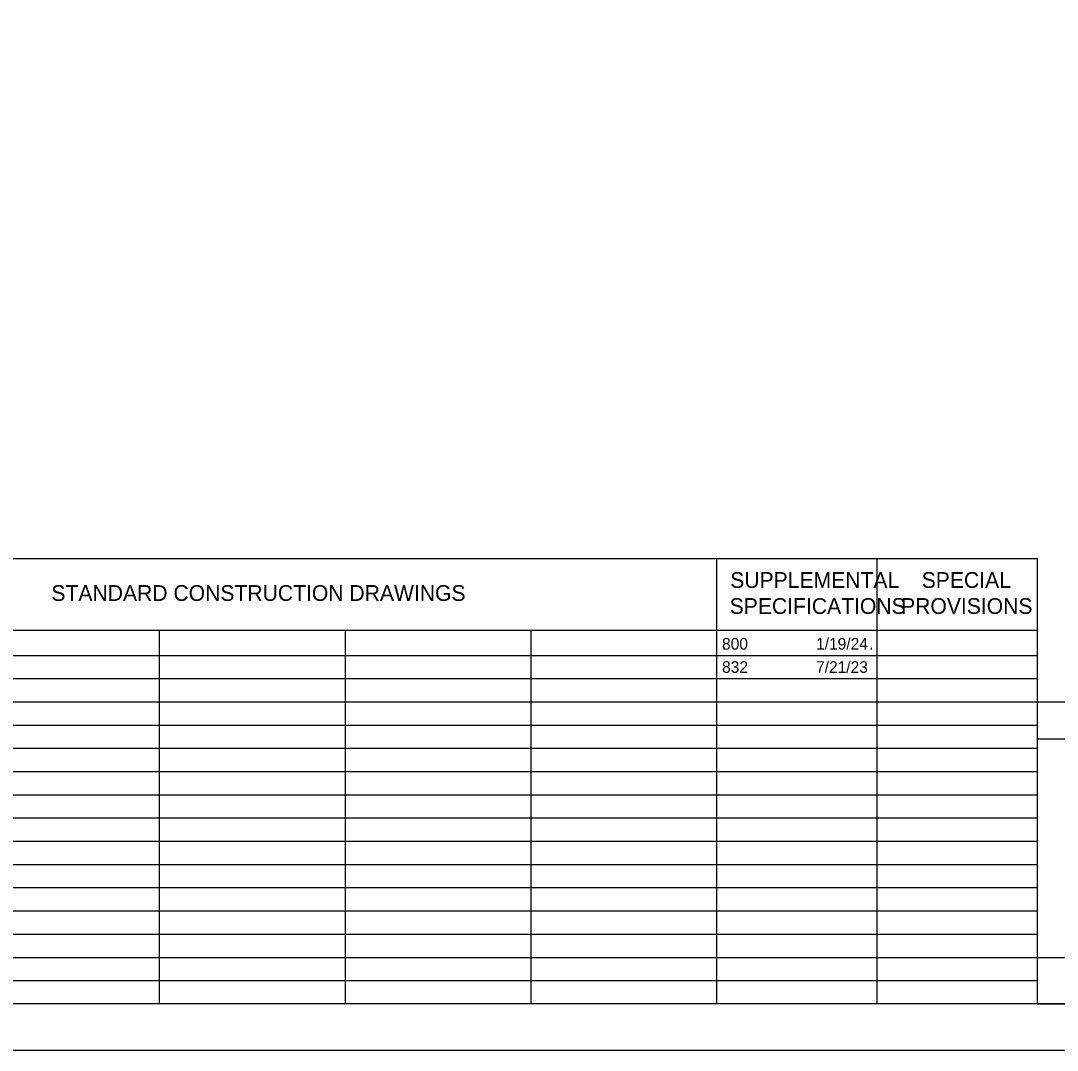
# Model space of a CAD drawing. Extents: x 0 to 34, y 0 to 22.
# Drawn here: x 12.66 to 23.81, y 0 to 11.08 of the extents above; entities that cross this region are included whole.
import ezdxf

# ---------------------------------------------------------------- set-up
doc = ezdxf.new("R2010")
doc.units = 0
for name, color, linetype in [('SH_Border', 7, 'Continuous'), ('SH_Cut_Line', 7, 'Continuous'), ('SH_Data', 7, 'Continuous'), ('SH_Text', 7, 'Continuous')]:
    doc.layers.add(name, color=color, linetype=linetype)

msp = doc.modelspace()

# ---------------------------------------------------------------- linework, layer by layer
at = {"layer": 'SH_Border'}
msp.add_lwpolyline([(1.5, 21.5), (33.5, 21.5), (33.5, 0.5), (1.5, 0.5)], close=True, dxfattribs=at)
at = {"layer": 'SH_Cut_Line'}
msp.add_lwpolyline([(0, 0), (34, 0), (34, 22), (0, 22)], close=True, dxfattribs=at)
at = {"layer": 'SH_Data'}
for p, q in [((10.15, 5.292), (23.6, 5.292)), ((20.15, 0.5), (20.15, 5.292)), ((21.875, 0.5), (21.875, 5.292)), ((23.6, 0.5), (23.6, 5.292)), ((10.15, 4.521), (23.6, 4.521)), ((14.15, 0.5), (14.15, 4.521)), ((16.15, 0.5), (16.15, 4.521)), ((18.15, 0.5), (18.15, 4.521)), ((10.15, 4.25), (23.6, 4.25)), ((10.15, 4), (23.6, 4)), ((10.15, 3.75), (23.6, 3.75)), ((23.6, 0.5), (23.6, 3.75)), ((23.6, 3.75), (26.4, 3.75)), ((10.15, 3.5), (23.6, 3.5)), ((23.6, 3.35), (26.4, 3.35)), ((10.15, 3.25), (23.6, 3.25)), ((10.15, 3), (23.6, 3)), ((10.15, 2.75), (23.6, 2.75)), ((10.15, 2.5), (23.6, 2.5)), ((10.15, 2.25), (23.6, 2.25)), ((10.15, 2), (23.6, 2)), ((10.15, 1.75), (23.6, 1.75)), ((10.15, 1.5), (23.6, 1.5)), ((10.15, 1.25), (23.6, 1.25)), ((10.15, 1), (23.6, 1)), ((10.15, 0.75), (23.6, 0.75)), ((23.6, 0.5), (26.4, 0.5)), ((23.6, 0.5), (26.4, 0.5))]:
    msp.add_line(p, q, dxfattribs=at)
msp.add_lwpolyline([(23.6, 0.5), (23.6, 1), (26.4, 1), (26.4, 0.5)], close=True, dxfattribs=at)

# ---------------------------------------------------------------- texts
at = {"layer": 'SH_Text'}
for s, height, p in [('SUPPLEMENTAL', 0.17, (20.293, 4.976)), ('SPECIAL', 0.17, (22.354, 4.976)), ('STANDARD CONSTRUCTION DRAWINGS', 0.17, (12.986, 4.836)), ('SPECIFICATIONS', 0.17, (20.287, 4.696)), ('PROVISIONS', 0.17, (22.132, 4.696)), ('800', 0.125, (20.205, 4.312)), ('1/19/24', 0.125, (21.217, 4.312)), ('.', 0.125, (20.205, 4.312)), ('.', 0.125, (21.789, 4.312)), ('832', 0.125, (20.205, 4.062)), ('7/21/23', 0.125, (21.217, 4.062))]:
    msp.add_text(s, height=height, dxfattribs=at).set_placement(p)

doc.saveas('drawing.dxf')
